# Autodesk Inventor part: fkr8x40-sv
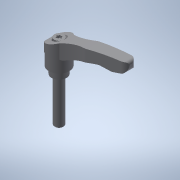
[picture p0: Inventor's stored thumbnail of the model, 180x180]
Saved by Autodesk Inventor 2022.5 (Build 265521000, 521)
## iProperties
Created: 2017-09
Part Number: fkr8x40-sv
Material: 一般
Document SubType Name: Modeling
Designer: imaocorp
Density: 1 g/cm^3
Appearance: 既定
Author: imaocorp
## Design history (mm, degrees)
node "fkr8x40-sv.x_t1"
node "fkr8x40-sv"
node "Base1"
